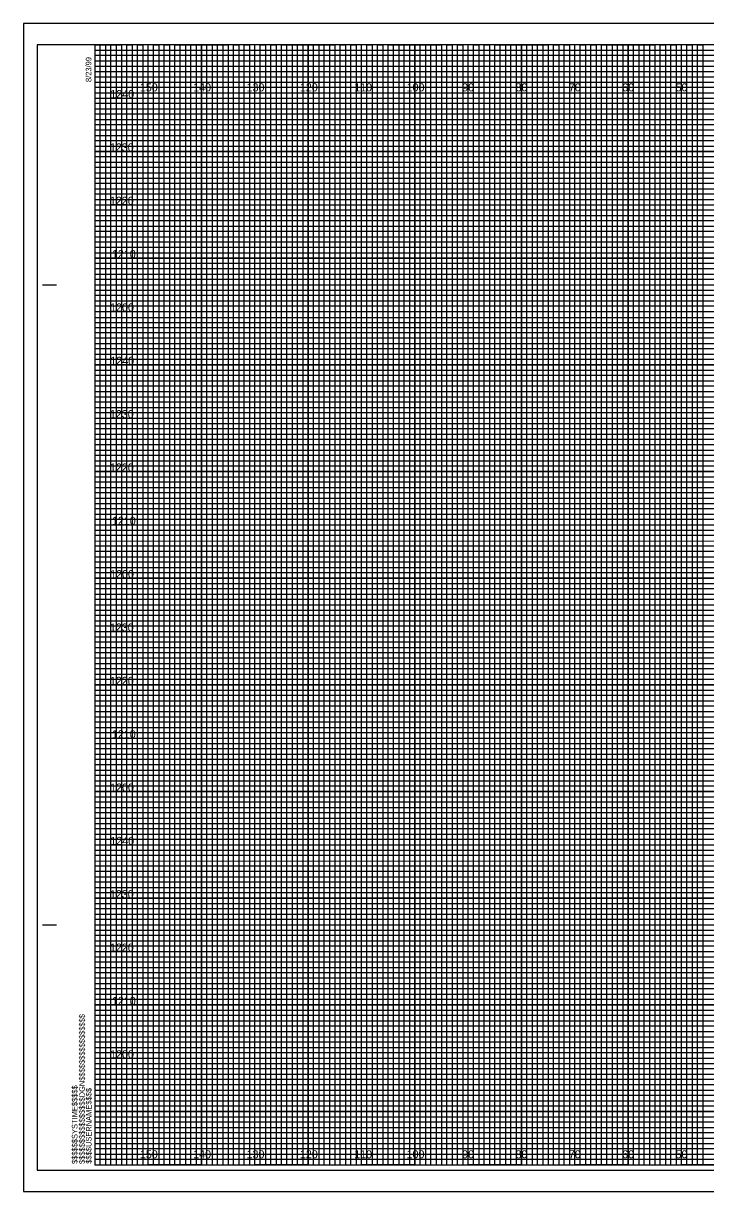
# Model space of a CAD drawing. Extents: x -13 to 323, y -5 to 214.
# Drawn here: x -13.4 to 114.5, y -5 to 214 of the extents above; entities that cross this region are included whole.
import ezdxf

# ---------------------------------------------------------------- set-up
doc = ezdxf.new("R2010")
doc.units = 0
for name, color, linetype in [('Prop XS Elevation Labels', 7, 'Continuous'), ('Prop XS Offset Labels', 7, 'Continuous'), ('Sheet Cross Section CELL', 7, 'Continuous'), ('Sheet Cross Section Grid Major CELL', 7, 'Continuous'), ('Sheet Cross Section Grid Middle CELL', 7, 'Continuous'), ('Sheet Cross Section Grid Minor 1 CELL', 7, 'Continuous'), ('Sheet Cross Section Grid Minor 2 CELL', 7, 'Continuous'), ('Sheet Cutting Line CELL', 7, 'Continuous'), ('Sheet DOT Grid CELL', 7, 'Continuous'), ('Sheet Plot Border Inside CELL', 7, 'Continuous'), ('Sheet Plot Border Outside CELL', 7, 'Continuous')]:
    doc.layers.add(name, color=color, linetype=linetype)

msp = doc.modelspace()

# ---------------------------------------------------------------- linework, layer by layer
at = {"layer": 'Sheet Cross Section CELL'}
for p, q in [((-9.8, 165), (-7.3, 165)), ((-9.7, 165), (-7.2, 165)), ((-9.8, 45), (-7.3, 45)), ((-9.7, 45), (-7.2, 45)), ((0, 0), (0, 0)), ((0, 0), (0, 0)), ((0, 0), (0, 0)), ((0, 0), (0, 0)), ((0, 0), (0, 0)), ((0, 0), (0, 0)), ((0, 0), (0, 0))]:
    msp.add_line(p, q, dxfattribs=at)
msp.add_lwpolyline([(320, 210), (0, 210), (0, 0), (320, 0)], close=True, dxfattribs=at)
at = {"layer": 'Sheet Cross Section Grid Major CELL'}
for p, q in [((10, 210), (0, 210)), ((10, 0), (10, 210)), ((30, 210), (20, 210)), ((20, 210), (20, 0)), ((30, 0), (30, 210)), ((50, 210), (40, 210)), ((40, 210), (40, 0)), ((50, 0), (50, 210)), ((70, 210), (60, 210)), ((60, 210), (60, 0)), ((70, 0), (70, 210)), ((90, 210), (80, 210)), ((80, 210), (80, 0)), ((90, 0), (90, 210)), ((110, 210), (100, 210)), ((100, 210), (100, 0)), ((110, 0), (110, 210)), ((20, 0), (10, 0)), ((40, 0), (30, 0)), ((60, 0), (50, 0)), ((80, 0), (70, 0)), ((100, 0), (90, 0)), ((120, 0), (110, 0))]:
    msp.add_line(p, q, dxfattribs=at)
for points in [[(0, 200), (320, 200), (320, 190), (0, 190)], [(0, 180), (320, 180), (320, 170), (0, 170)], [(0, 160), (320, 160), (320, 150), (0, 150)], [(0, 140), (320, 140), (320, 130), (0, 130)], [(0, 120), (320, 120), (320, 110), (0, 110)], [(0, 100), (320, 100), (320, 90), (0, 90)], [(0, 80), (320, 80), (320, 70), (0, 70)], [(0, 60), (320, 60), (320, 50), (0, 50)], [(0, 40), (320, 40), (320, 30), (0, 30)], [(0, 20), (320, 20), (320, 10), (0, 10)]]:
    msp.add_lwpolyline(points, dxfattribs=at)
at = {"layer": 'Sheet Cross Section Grid Middle CELL'}
for points in [[(0, 210), (5, 210), (5, 0), (15, 0), (15, 210), (25, 210), (25, 0), (35, 0), (35, 210), (45, 210), (45, 0), (55, 0), (55, 210), (65, 210), (65, 0), (75, 0), (75, 210), (85, 210), (85, 0), (95, 0), (95, 210), (105, 210), (105, 0), (115, 0)], [(0, 205), (275, 205)], [(0, 185), (320, 185), (320, 195), (0, 195)], [(0, 165), (320, 165), (320, 175), (0, 175)], [(0, 145), (320, 145), (320, 155), (0, 155)], [(0, 125), (320, 125), (320, 135), (0, 135)], [(0, 105), (320, 105), (320, 115), (0, 115)], [(0, 85), (320, 85), (320, 95), (0, 95)], [(0, 65), (320, 65), (320, 75), (0, 75)], [(0, 45), (320, 45), (320, 55), (0, 55)], [(0, 25), (320, 25), (320, 35), (0, 35)], [(0, 5), (320, 5), (320, 15), (0, 15)]]:
    msp.add_lwpolyline(points, dxfattribs=at)
at = {"layer": 'Sheet Cross Section Grid Minor 1 CELL'}
for p, q in [((0, 209), (260, 209)), ((260, 207.98), (0, 207.98)), ((0, 207.98), (0, 207)), ((0, 207), (260, 207)), ((260, 205.89), (0, 205.89)), ((0, 205.89), (0, 204)), ((0, 204), (320, 204))]:
    msp.add_line(p, q, dxfattribs=at)
for points in [[(0, 203), (270, 203), (320, 203), (320, 202), (0, 202)], [(0, 201), (320, 201), (320, 199), (0, 199)], [(0, 198), (320, 198), (320, 197), (0, 196.98)], [(0, 196), (320, 196), (320, 194), (0, 194)], [(0, 193), (320, 193), (320, 192), (0, 192)], [(0, 191), (320, 191), (320, 189), (0, 189)], [(0, 188), (320, 188), (320, 187), (0, 187)], [(0, 186), (320, 186), (320, 184), (0, 184)], [(0, 183), (320, 183), (320, 182), (0, 182)], [(0, 181), (320, 181), (320, 179), (0, 179)], [(0, 178), (320, 178), (320, 177), (0, 177)], [(0, 176), (320, 176), (320, 173.95), (320, 173), (320, 172), (0, 172)], [(0, 174), (320, 174), (320, 173), (0, 173)], [(0, 171), (320, 171), (320, 169), (0, 169.03)], [(0, 169.03), (320, 169), (320, 168), (0, 168)], [(0, 167), (320, 167), (320, 166), (0, 166)], [(0, 164), (320, 164), (320, 163), (0, 163)], [(0, 162), (320, 162), (320, 161), (0, 161)], [(-0.07, 158.89), (320, 158.89), (320, 157.88), (-0.07, 157.88)], [(0, 157), (320, 157), (320, 156), (0, 156)], [(0, 154), (320, 154), (320, 153), (0, 153)], [(0, 152), (320, 152), (320, 151), (0, 151)], [(0, 149), (320, 149), (320, 148), (0, 148)], [(0, 147), (320, 147), (320, 146), (0, 146)], [(0, 144), (320, 144), (320, 143), (0, 143)], [(0, 142), (320, 142), (320, 141), (0, 141)], [(0, 139), (320, 139), (319.99, 137.98), (0, 138)], [(0, 137), (320, 137), (320, 136), (0, 136)], [(0, 134), (320, 134), (320, 133), (0, 133)], [(0, 132), (320, 132), (320, 131), (0, 131)], [(0, 129), (320, 129), (320, 128), (0, 128)], [(0, 127), (320, 127), (320, 126), (0, 126)], [(0, 124), (320, 124), (320, 123), (0, 123)], [(0, 122), (320, 122), (320, 121), (0, 121)], [(0, 119), (320, 119), (320, 118), (0, 118)], [(0, 116.99), (320.07, 116.91), (320, 116), (0, 116)], [(0, 114), (320, 114), (320, 113), (0, 113)], [(0, 112), (320, 112), (320, 111), (0, 111)], [(0, 109), (320, 109), (320, 108), (0, 108)], [(0, 107), (320, 107), (320, 106), (0, 106)], [(0, 104), (320, 104), (320, 103), (0, 103)], [(0, 102), (320, 102), (320, 101), (0, 101)], [(0, 99), (320, 99), (320, 98), (0, 98)], [(0, 97), (320, 97), (320, 96), (0, 96)], [(0, 94), (320, 94), (320, 93), (0, 93)], [(0, 92), (320, 92), (320, 91), (0, 91)], [(0, 89), (320, 89), (320, 88), (0, 88)], [(0, 87), (320, 87), (320, 86), (0, 86)], [(0, 84), (320, 84), (320, 83), (0, 83)], [(0, 82), (320, 82), (320, 81), (0, 81)], [(0, 79), (320, 79), (319.99, 77.98), (0, 78)], [(0, 77), (320, 77), (320, 76), (0, 76)], [(0, 74), (320, 74), (320, 73), (0, 73)], [(0, 72), (320, 72), (320, 71), (0, 71)], [(0, 69), (320, 69), (320, 68), (0, 68)], [(0, 67), (320, 67), (320, 66), (0, 66)], [(0, 64), (320, 64), (320, 63), (0, 63)], [(0, 62), (320, 62), (320, 61), (0, 61)], [(0, 59), (320, 59), (320, 58), (0, 58)], [(0, 56.99), (320.07, 56.91), (320, 56), (0, 56)], [(0, 54), (320, 54), (320, 53), (0, 53)], [(0, 52), (320, 52), (320, 51), (0, 51)], [(0, 49), (320, 49), (320, 48), (0, 48)], [(0, 47), (320, 47), (320, 46), (0, 46)], [(0, 44), (320, 44), (320, 43), (0, 43)], [(0, 42), (320, 42), (320, 41), (0, 41)], [(0, 39), (320, 39), (320, 38), (0, 38)], [(0, 37), (320, 37), (320, 36), (0, 36)], [(0, 34), (320, 34), (320, 33), (0, 33)], [(0, 32), (320, 32), (320, 31), (0, 31)], [(0, 29), (320, 29), (320, 28), (0, 28)], [(0, 27), (320, 27), (320, 26), (0, 26)], [(0, 24), (320, 24), (320, 23), (0, 23)], [(0, 22), (320, 22), (320, 21), (0, 21)], [(0, 19), (320, 19), (320, 18), (0, 18)], [(0, 17), (320, 17), (320, 16), (0, 16)], [(0, 14), (320, 14), (320, 13), (0, 13)], [(0, 12), (320, 12), (320, 11), (0, 11)], [(0, 9), (320, 9), (320, 8), (0, 8)], [(0, 7), (320, 7), (320, 6), (0, 6)], [(0, 4), (320, 4), (320, 3), (0, 3)], [(0, 2), (320, 2), (320, 1), (0, 1)]]:
    msp.add_lwpolyline(points, dxfattribs=at)
at = {"layer": 'Sheet Cross Section Grid Minor 2 CELL'}
for points in [[(0, 0), (1, 0), (1, 210), (2, 210), (2, 0)], [(2, 0), (3, 0), (3, 210), (4, 210), (4, 0)], [(5, 0), (6, 0), (6, 210), (7, 210), (7, 0)], [(7, 0), (8, 0), (8, 210), (9, 210), (9, 0)], [(10, 0), (11, 0), (11, 210), (12, 210), (12, 0)], [(12, 0), (13, 0), (13, 210), (14, 210), (14, 0)], [(15, 0), (16, 0), (16, 210), (17, 210), (17, 0)], [(17, 0), (18, 0), (18, 210), (19, 210), (19, 0)], [(20, 0), (21, 0), (21, 210), (22, 210), (22, 0)], [(22, 0), (23, 0), (23, 210), (24, 210), (24, 0)], [(25, 0), (26, 0), (26, 210), (27, 210), (27, 0)], [(27, 0), (28, 0), (28, 210), (29, 210), (29, 0)], [(30, 0), (31, 0), (31, 210), (32, 210), (32, 0)], [(32, 0), (33, 0), (33, 210), (34, 210), (34, 0)], [(35, 0), (36, 0), (36, 210), (37, 210), (37, 0)], [(37, 0), (38, 0), (38, 210), (39, 210), (39, 0)], [(40, 0), (41, 0), (41, 210), (42, 210), (42, 0)], [(42, 0), (43, 0), (43, 210), (44, 210), (44, 0)], [(45, 0), (46, 0), (46, 210), (47, 210), (47, 0)], [(47, 0), (48, 0), (48, 210), (49, 210), (49, 0)], [(50, 0), (51, 0), (51, 210), (52, 210), (52, 0)], [(52, 0), (53, 0), (53, 210), (54, 210), (54, 0)], [(55, 0), (56, 0), (56, 210), (57, 210), (57, 0)], [(57, 0), (58, 0), (58, 210), (59, 210), (59, 0)], [(60, 0), (61, 0), (61, 210), (62, 210), (62, 0)], [(62, 0), (63, 0), (63, 210), (64, 210), (64, 0)], [(65, 0), (66, 0), (66, 210), (67, 210), (67, 0)], [(67, 0), (68, 0), (68, 210), (69, 210), (69, 0)], [(70, 0), (71, 0), (71, 210), (72, 210), (72, 0)], [(72, 0), (73, 0), (73, 210), (74, 210), (74, 0)], [(75, 0), (76, 0), (76, 210), (77, 210), (77, 0)], [(77, 0), (78, 0), (78, 210), (79, 210), (79, 0)], [(80, 0), (81, 0), (81, 210), (82, 210), (82, 0)], [(82, 0), (83, 0), (83, 210), (84, 210), (84, 0)], [(85, 0), (86, 0), (86, 210), (87, 210), (87, 0)], [(87, 0), (88, 0), (88, 210), (89, 210), (89, 0)], [(90, 0), (91, 0), (91, 210), (92, 210), (92, 0)], [(92, 0), (93, 0), (93, 210), (94, 210), (94, 0)], [(95, 0), (96, 0), (96, 210), (97, 210), (97, 0)], [(97, 0), (98, 0), (98, 210), (99, 210), (99, 0)], [(100, 0), (101, 0), (101, 210), (102, 210), (102, 0)], [(102, 0), (103, 0), (103, 210), (104, 210), (104, 0)], [(105, 0), (106, 0), (106, 210), (107, 210), (107, 0)], [(107, 0), (108, 0), (108, 210), (109, 210), (109, 0)], [(110, 0), (111, 0), (111, 210), (112, 210), (112, 0)], [(112, 0), (113, 0), (113, 210), (114, 210), (114, 0)]]:
    msp.add_lwpolyline(points, dxfattribs=at)
at = {"layer": 'Sheet Cutting Line CELL'}
for p, q in [((323.3, 214), (-13.4, 214)), ((-13.4, 214), (-13.4, -5)), ((-13.4, -5), (323.3, -5))]:
    msp.add_line(p, q, dxfattribs=at)
at = {"layer": 'Sheet DOT Grid CELL'}
for p, q in [((10, 0), (10, 210)), ((20, 0), (20, 210)), ((30, 0), (30, 210)), ((40, 0), (40, 210)), ((50, 0), (50, 210)), ((60, 0), (60, 210)), ((70, 0), (70, 210)), ((80, 0), (80, 210)), ((90, 0), (90, 210)), ((100, 0), (100, 210)), ((110, 0), (110, 210)), ((0, 200), (320, 200)), ((0, 190), (320, 190)), ((0, 180), (320, 180)), ((0, 170), (320, 170)), ((0, 160), (320, 160)), ((0, 150), (320, 150)), ((0, 140), (320, 140)), ((0, 130), (320, 130)), ((0, 120), (320, 120)), ((0, 110), (320, 110)), ((0, 100), (320, 100)), ((0, 90), (320, 90)), ((0, 80), (320, 80)), ((0, 70), (320, 70)), ((0, 60), (320, 60)), ((0, 50), (320, 50)), ((0, 40), (320, 40)), ((0, 30), (320, 30)), ((0, 20), (320, 20)), ((0, 10), (320, 10))]:
    msp.add_line(p, q, dxfattribs=at)
at = {"layer": 'Sheet Plot Border Inside CELL'}
msp.add_lwpolyline([(-10.8, -1), (322.4, -1), (322.4, 210), (-10.8, 210)], close=True, dxfattribs=at)
at = {"layer": 'Sheet Plot Border Outside CELL'}
msp.add_lwpolyline([(-13.4, -5), (323.3, -5), (323.3, 214), (-13.4, 214)], close=True, dxfattribs=at)

# ---------------------------------------------------------------- texts
at = {"layer": 'Prop XS Elevation Labels'}
for s, p in [('1240', (2.9, 200)), ('1230', (2.82, 190)), ('1220', (2.83, 180)), ('1210', (3.2, 170)), ('1200', (2.87, 160)), ('1240', (2.9, 150)), ('1230', (2.82, 140)), ('1220', (2.83, 130)), ('1210', (3.2, 120)), ('1200', (2.87, 110)), ('1230', (2.82, 100)), ('1220', (2.83, 90)), ('1210', (3.2, 80)), ('1200', (2.87, 70)), ('1240', (2.9, 60)), ('1230', (2.82, 50)), ('1220', (2.83, 40)), ('1210', (3.2, 30)), ('1200', (2.87, 20))]:
    msp.add_text(s, height=1.5, dxfattribs=at).set_placement(p)
at = {"layer": 'Prop XS Offset Labels'}
for s, p in [('150', (8.44, 201.25)), ('140', (18.44, 201.25)), ('130', (28.44, 201.25)), ('120', (38.44, 201.25)), ('110', (48.62, 201.25)), ('100', (58.44, 201.25)), ('90', (68.86, 201.25)), ('80', (78.86, 201.25)), ('70', (88.86, 201.25)), ('60', (98.86, 201.25)), ('50', (108.86, 201.25)), ('150', (8.44, 1.25)), ('140', (18.44, 1.25)), ('130', (28.44, 1.25)), ('120', (38.44, 1.25)), ('110', (48.62, 1.25)), ('100', (58.44, 1.25)), ('90', (68.86, 1.25)), ('80', (78.86, 1.25)), ('70', (88.86, 1.25)), ('60', (98.86, 1.25)), ('50', (108.86, 1.25))]:
    msp.add_text(s, height=1.5, dxfattribs=at).set_placement(p)
at = {"layer": 'Sheet Cross Section CELL'}
for s, p in [('8/23/99', (-0.65, 203)), ('$$$$$$$$$$$$$$$$DGN$$$$$$$$$$$$$$$$', (-1.88, 0.18)), ('$$$$$$SYSTIME$$$$$', (-3.26, 0.18)), ('$$$$USERNAME$$$$', (-0.62, 0.23))]:
    msp.add_text(s, height=1.05, rotation=90, dxfattribs=at).set_placement(p)

doc.saveas('drawing.dxf')
